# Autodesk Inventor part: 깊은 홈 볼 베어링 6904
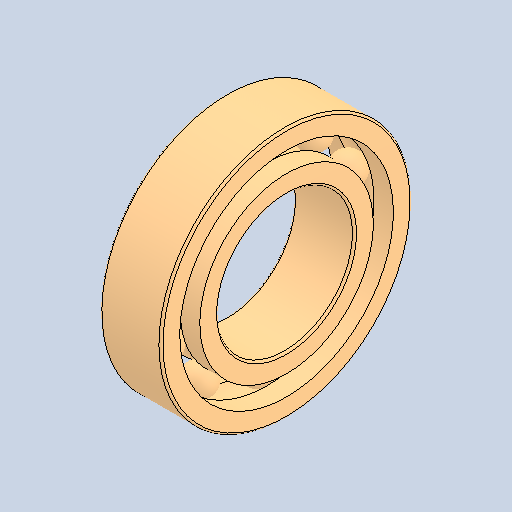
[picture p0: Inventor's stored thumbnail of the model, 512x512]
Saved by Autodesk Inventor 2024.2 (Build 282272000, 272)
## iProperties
Created: 2025-09
Part Number: 깊은 홈 볼 베어링 6904
Material: 강철, 연강
Description: 깊은 그루브 볼 베어링
Document SubType Name: Modeling
Designer: home
Density: 7.85 g/cm^3
Appearance: 기본값
Author: jhkim
Sending System: Autodesk Inventor 2026
Preprocessor: ST-DEVELOPER v20.1
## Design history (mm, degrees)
feature "Solid1"
feature "Solid1:1"
feature "Solid1:2"
feature "Solid1:3"
feature "Solid1:4"
feature "Solid1:5"
feature "Solid1:6"
feature "Solid1:7"
feature "Solid1:8"
feature "Solid1:9"
feature "Solid1:10"
feature "Solid1:11"
node "솔리드1"
node "솔리드2"
node "솔리드3"
node "솔리드4"
node "솔리드5"
node "솔리드6"
node "솔리드7"
node "솔리드8"
node "솔리드9"
node "솔리드10"
node "솔리드11"
node "솔리드12"
